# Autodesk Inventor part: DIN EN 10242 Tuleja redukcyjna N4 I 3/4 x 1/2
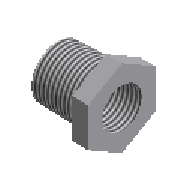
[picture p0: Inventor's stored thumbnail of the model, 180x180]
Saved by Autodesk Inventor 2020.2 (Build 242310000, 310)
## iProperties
Manager: www.cadconsulting.pl
Company: Fabian Stasiak CAD Consulting
IsCustomPart: 0
Created: 2014-02
Part Number: DIN EN 10242 Tuleja redukcyjna N4 I 3/4 x 1/2
Material: Żelazo, ciągliwe
Description: Tuleja redukcyjna
Document SubType Name: Modeling
Standard: DIN EN 10242
Designer: F.Stasiak
Standards Organization: DIN
Language: pl-PL
Size Designation: 3/4 x 1/2
Categories: <MemberInstance><Categories><Category DisplayName="Rury cienko- i grubościenne" InternalName="4347fa0f-2144-441d-94cd-e3e15c92b736" Mnemonic="TUBEANDPIPE"><Cate
Density: 7.15 g/cm^3
Appearance: Częściowo polerowana
Catalog Web Link: www.expertbooks.pl
NAME: PIPING: DIN EN 10242 Reducing Bushing N4 I
DATA: <meta><inlinegroups number="1" deflen="2"></inlinegroups><connections number="2"></connections><angles><a>3.14159265358979</a></angles></meta>
Author: F.Stasiak
Subject: Zbiór ćwiczeń. Autodesk Inventor 2020. Kurs Professional
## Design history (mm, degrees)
sketch "Sketch1"
  geometry: L1 (0, 0)-(-26, 0); L2 (-26, 0)-(-26, 9.896); L3 (-26, 16)-(-20, 16); L4 (-20, 16)-(-20, 16); L5 (-26, 16)-(-26, 9.896); L6 (-20, 16)-(-20, 13.548); L7 (-20, 13.548)-(0, 12.923); L8 (0, 12.923)-(0, 9.897); L9 (0, 9.897)-(-26, 9.896); L10 (0, 9.897)-(0, 0); L11 (-13, 9.896)-(-13, 0); L12 (-20, 13.548)-(-20, 0); L13 (-9.53, 13.22)-(-9.53, 0)
  constraints: 26 end point, 5 perpendicular, 4 parallel, 4 point on line, 2 horizontal, 2 midpoint, 1 vertical
  dimensions: "d0" = 19.793 diameter of L2.end L1 (= MD); "d1" = 32 diameter of L3 L1 (= S); "d6" = 26 distance of L1.start L1.end (= A); "d7" = 6 distance of L3.start L3.end (= m1); "d10" = 1.78991 deg angle of L1 L7; "d37" = 13 distance of L1.end L11.end (= A - Z); "d38" = 9.53 distance between parallel lines of L10 L13 (= a); "d39" = 26.441 diameter of L13.start L1 (= DD)
revolve "Revolve1" sketch "Sketch1" stored, may be unused: angle "d8" = 90 deg
sketch "Sketch2"
  geometry: L1 (-16, 9.238)-(0, 18.475); L2 (0, 18.475)-(16, 9.238); L3 (16, 9.238)-(16, -9.238); L4 (16, -9.238)-(0, -18.475); L5 (0, -18.475)-(-16, -9.238); L6 (-16, -9.238)-(-16, 9.238); 4 further points
  constraints: 12 end point, 1 coincident, 1 horizontal alignment, 1 midpoint, 1 vertical, 12 other
extrude "Extrude1" join sketch "Sketch2" distance "d2" = 6 (= m1); taper "d3" = 0 deg
workpoint "Work Point1"
workpoint "Work Point2"
workaxis "Work Axis1"
workpoint "Work Point3"
workpoint "Work Point4"
workaxis "Work Axis2"
workpoint "Work Point5"
body "Solid1"
feature "Gwint1" dims "d11" = 25.4, "d12" = 0
feature "Gwint2" dims "d40" = 13 (= A - Z), "d41" = 0
other parameters: "OD" = 27.2 [user parameter], "MD" = 19.793 [user parameter; used in 1 equation term], "m1" = 6 [user parameter; used in 2 equation terms], "S" = 32 [user parameter; used in 1 equation term], "A" = 26 [user parameter; used in 3 equation terms], "Z" = 13 [user parameter; used in 2 equation terms], "DD" = 26.441 [user parameter; used in 1 equation term], "a" = 9.53 [user parameter; used in 1 equation term], "Size_Designation" = 12.345 [user parameter]
